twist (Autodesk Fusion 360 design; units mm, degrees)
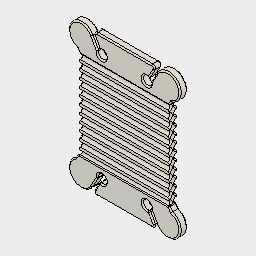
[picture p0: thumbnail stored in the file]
canvas "Canvas1"
sketch "Sketch1"
  line L1 (10.2523, 22.2547) -> (12.5554, 26.4455)
  line L2 (11.5624, 27.0067) -> (9.5009, 23.2556)
  line L3 (21.7915, 29.3721) -> (-22.6881, 29.3721)
  line L4 (21.7915, -29.0348) -> (21.7915, 29.3721)
  line L5 (-22.6881, -29.0348) -> (21.7915, -29.0348)
  line L6 (-22.6881, 29.3721) -> (-22.6881, -29.0348)
  line L7 (18.4916, 19.285) -> (17.5683, 17.8706)
  line L8 (17.5683, 17.8706) -> (17.5683, 0.1687)
  line L9 (-11.1488, 22.2547) -> (-13.4519, 26.4455)
  line L10 (-12.4589, 27.0067) -> (-10.3974, 23.2556)
  line L11 (-19.3881, 19.285) -> (-18.4648, 17.8706)
  line L12 (-18.4648, 17.8706) -> (-18.4648, 0.1687)
  line L13 (-0.4483, 29.3721) -> (-0.4483, 28.4712)
  line L14 (10.5015, 28.4712) -> (-11.398, 28.4712)
  line L15 (11.5624, 27.0067) -> (9.5009, 23.2556)
  line L16 (-11.398, 28.4712) -> (10.5015, 28.4712)
  line L17 (-0.4483, 29.3721) -> (-0.4483, 28.4712)
  line L18 (17.5683, 17.8706) -> (17.5683, 0.1687)
  line L19 (18.4916, 19.285) -> (17.5683, 17.8706)
  line L20 (10.2523, 22.2547) -> (12.5554, 26.4455)
  line L21 (-18.4648, 17.8706) -> (-18.4648, 0.1687)
  line L22 (-19.3881, 19.285) -> (-18.4648, 17.8706)
  line L23 (-22.6881, 29.3721) -> (21.7915, 29.3721)
  line L24 (-12.4589, 27.0067) -> (-10.3974, 23.2556)
  line L25 (-11.1488, 22.2547) -> (-13.4519, 26.4455)
  line L26 (-11.1488, -21.9174) -> (-13.4519, -26.1081)
  line L27 (17.5683, -17.5333) -> (17.5683, 0.1687)
  line L28 (11.5624, -26.6694) -> (9.5009, -22.9183)
  line L29 (21.7915, -29.0348) -> (-22.6881, -29.0348)
  line L30 (18.4916, -18.9477) -> (17.5683, -17.5333)
  line L31 (-19.3881, -18.9477) -> (-18.4648, -17.5333)
  line L32 (-11.1488, -21.9174) -> (-13.4519, -26.1081)
  line L33 (10.2523, -21.9174) -> (12.5554, -26.1081)
  line L34 (10.2523, -21.9174) -> (12.5554, -26.1081)
  line L35 (-18.4648, -17.5333) -> (-18.4648, 0.1687)
  line L36 (-19.3881, -18.9477) -> (-18.4648, -17.5333)
  line L37 (-12.4589, -26.6694) -> (-10.3974, -22.9183)
  line L38 (-0.4483, -29.0348) -> (-0.4483, -28.1338)
  line L39 (10.5015, -28.1338) -> (-11.398, -28.1338)
  line L40 (11.5624, -26.6694) -> (9.5009, -22.9183)
  line L41 (-11.398, -28.1338) -> (10.5015, -28.1338)
  line L42 (-0.4483, -29.0348) -> (-0.4483, -28.1338)
  line L43 (-22.6881, -29.0348) -> (21.7915, -29.0348)
  line L44 (-12.4589, -26.6694) -> (-10.3974, -22.9183)
  line L45 (-18.4648, -17.5333) -> (-18.4648, 0.1687)
  line L46 (18.4916, -18.9477) -> (17.5683, -17.5333)
  line L47 (17.5683, -17.5333) -> (17.5683, 0.1687)
  arc A1 centre (10.686, 27.4883) radius 1 clockwise from (10.5015, 28.4712) to (11.5624, 27.0067)
  arc A2 centre (8.5696, 21.774) radius 1.75 clockwise from (10.2523, 22.2547) to (9.5009, 23.2556)
  arc A3 centre (16.9372, 24.0373) radius 5 clockwise from (12.5554, 26.4455) to (18.4916, 19.285)
  arc A4 centre (-11.5826, 27.4883) radius 1 clockwise from (-12.4589, 27.0067) to (-11.398, 28.4712)
  arc A5 centre (-17.8338, 24.0373) radius 5 clockwise from (-19.3881, 19.285) to (-13.4519, 26.4455)
  arc A6 centre (-9.4661, 21.774) radius 1.75 clockwise from (-10.3974, 23.2556) to (-11.1488, 22.2547)
  arc A7 centre (8.5696, 21.774) radius 1.75 clockwise from (10.2523, 22.2547) to (9.5009, 23.2556)
  arc A8 centre (-9.4661, 21.774) radius 1.75 clockwise from (-10.3974, 23.2556) to (-11.1488, 22.2547)
  arc A9 centre (-17.8338, 24.0373) radius 5 clockwise from (-19.3881, 19.285) to (-13.4519, 26.4455)
  arc A10 centre (10.686, 27.4883) radius 1 clockwise from (10.5015, 28.4712) to (11.5624, 27.0067)
  arc A11 centre (16.9372, 24.0373) radius 5 clockwise from (12.5554, 26.4455) to (18.4916, 19.285)
  arc A12 centre (-11.5826, 27.4883) radius 1 clockwise from (-12.4589, 27.0067) to (-11.398, 28.4712)
  arc A13 centre (16.9372, -23.7) radius 5 clockwise from (18.4916, -18.9477) to (12.5554, -26.1081)
  arc A14 centre (-17.8338, -23.7) radius 5 clockwise from (-13.4519, -26.1081) to (-19.3881, -18.9477)
  arc A15 centre (-9.4661, -21.4367) radius 1.75 clockwise from (-11.1488, -21.9174) to (-10.3974, -22.9183)
  arc A16 centre (8.5696, -21.4367) radius 1.75 clockwise from (9.5009, -22.9183) to (10.2523, -21.9174)
  arc A17 centre (-9.4661, -21.4367) radius 1.75 clockwise from (-11.1488, -21.9174) to (-10.3974, -22.9183)
  arc A18 centre (-17.8338, -23.7) radius 5 clockwise from (-13.4519, -26.1081) to (-19.3881, -18.9477)
  arc A19 centre (16.9372, -23.7) radius 5 clockwise from (18.4916, -18.9477) to (12.5554, -26.1081)
  arc A20 centre (8.5696, -21.4367) radius 1.75 clockwise from (9.5009, -22.9183) to (10.2523, -21.9174)
  arc A21 centre (-11.5826, -27.151) radius 1 clockwise from (-11.398, -28.1338) to (-12.4589, -26.6694)
  arc A22 centre (10.686, -27.151) radius 1 clockwise from (11.5624, -26.6694) to (10.5015, -28.1338)
  arc A23 centre (-11.5826, -27.151) radius 1 clockwise from (-11.398, -28.1338) to (-12.4589, -26.6694)
  arc A24 centre (10.686, -27.151) radius 1 clockwise from (11.5624, -26.6694) to (10.5015, -28.1338)
  dimension "d1" diameter A3 = 10
  dimension "d2" diameter A2 = 3.5
  dimension "d3" diameter A1 = 2
extrude "Extrude1" new body sketch "Sketch1" profile of A3 A2 L1 L2 A1 L7 L8 A4 L9 L10 L11 L12 A5 A6 L14 L15 A7 L16 L18 L19 L20 L21 L22 L24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 blind 3
sketch "Sketch2" plane through (-18.4648, 0, 0) normal (-1, 0, 0) x axis (0, 0, 1)
  line L1 (0, -17.5333) -> (0, 17.8706)
  line L2 (3, -17.5333) -> (0, -17.5333)
  line L3 (3, 17.8706) -> (3, -17.5333)
  line L4 (0, 17.8706) -> (3, 17.8706)
  line L5 (0, 29.3721) -> (0, -29.0348)
  line L6 (-0.25, 16.8706) -> (3.25, 16.8706)
  circle C1 centre (3.25, 16.8706) radius 1
  circle C2 centre (-0.25, 16.8706) radius 1
  point P6 (3.25, 16.8706)
  point P9 (-0.25, 16.8706)
  dimension "d6" diameter C1 = 2
  dimension "d8" diameter C2 = 2 (= "d6")
  dimension "d10" distance L3 P6 = 0.25
  dimension "d11" distance L5 P9 = 0.25 (= "d10")
extrude "Extrude2" cut sketch "Sketch2" profile of L1 L3 C1 L5 C2 to an object
rectangular_pattern "R-Pattern1" countU 12 uSpaceDistance 33.436 vSpaceDistance 0
fillet "Fillet1" radius 0.5
fillet "Fillet2" radius 0.5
